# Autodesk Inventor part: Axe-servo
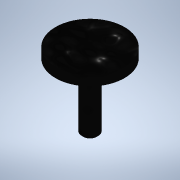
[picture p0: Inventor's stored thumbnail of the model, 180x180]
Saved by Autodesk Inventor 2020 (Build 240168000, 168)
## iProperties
Created: 2023-10
Part Number: Axe-servo
Material: Générique
Document SubType Name: Modeling
Designer: bruno
Density: 1 g/cm^3
Appearance: Noir
Author: bruno
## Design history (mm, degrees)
sketch "Esquisse1"
  geometry: L1 (0, 0)-(-3, 0); L2 (-3, 0)-(-3, 10.5); L3 (-3, 10.5)-(0, 10.5); L4 (0, 10.5)-(0, 0); L5 (-3, 5.759)-(-4.243, 5.759); L6 (-4.743, 5.259)-(-4.743, 0); L7 (-4.743, 0)-(-3, 0); L8 (-3, 0)-(-3, 5.759); L9 (-4.743, 0)-(-22.743, 0); L10 (-22.743, 0)-(-22.743, 2); L11 (-22.243, 2.5)-(-4.743, 2.5); L12 (-4.743, 2.5)-(-4.743, 0); L13 (-22.243, 2.5)-(-22.743, 2); L14 (-4.243, 5.759)-(-4.743, 5.259); 4 further points
  constraints: 28 end point, 6 parallel, 5 point on line, 3 horizontal, 3 perpendicular
  dimensions: "d0" = 3 distance of L2.end L3.end; "d1" = 10.5 distance of L1.end L2.end; "d2" = 18 distance of point (-22.743, 2.5) L11.end; "d3" = 2.5 distance of L9.end point (-22.743, 2.5); "d4" = 0.5 distance of L11.start point (-22.743, 2.5); "d5" = 0.5 distance of L10.end point (-22.743, 2.5) (= d4); "d6" = 0.5 distance of L5.end point (-4.743, 5.759) (= d4); "d7" = 0.5 distance of L6.start point (-4.743, 5.759) (= d6)
revolve "Révolution1" sketch "Esquisse1" stored, may be unused: angle "d8" = 90 deg
node "Solide1"
